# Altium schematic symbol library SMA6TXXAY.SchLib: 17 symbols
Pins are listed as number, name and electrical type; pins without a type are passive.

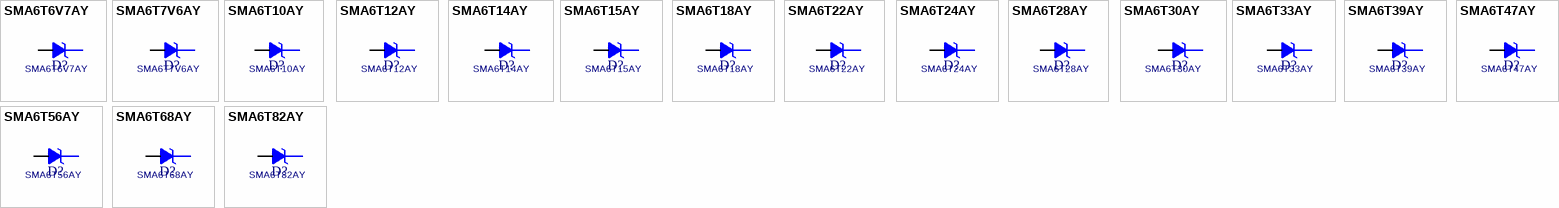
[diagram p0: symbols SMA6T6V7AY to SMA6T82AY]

## SMA6T6V7AY
designator D?
footprint ST_SMA
pins: 1 K, 2 A

## SMA6T7V6AY
designator D?
footprint ST_SMA
pins: 1 K, 2 A

## SMA6T10AY
designator D?
footprint ST_SMA
pins: 1 K, 2 A

## SMA6T12AY
designator D?
footprint ST_SMA
pins: 1 K, 2 A

## SMA6T14AY
designator D?
footprint ST_SMA
pins: 1 K, 2 A

## SMA6T15AY
designator D?
footprint ST_SMA
pins: 1 K, 2 A

## SMA6T18AY
designator D?
footprint ST_SMA
pins: 1 K, 2 A

## SMA6T22AY
designator D?
footprint ST_SMA
pins: 1 K, 2 A

## SMA6T24AY
designator D?
footprint ST_SMA
pins: 1 K, 2 A

## SMA6T28AY
designator D?
footprint ST_SMA
pins: 1 K, 2 A

## SMA6T30AY
designator D?
footprint ST_SMA
pins: 1 K, 2 A

## SMA6T33AY
designator D?
footprint ST_SMA
pins: 1 K, 2 A

## SMA6T39AY
designator D?
footprint ST_SMA
pins: 1 K, 2 A

## SMA6T47AY
designator D?
footprint ST_SMA
pins: 1 K, 2 A

## SMA6T56AY
designator D?
footprint ST_SMA
pins: 1 K, 2 A

## SMA6T68AY
designator D?
footprint ST_SMA
pins: 1 K, 2 A

## SMA6T82AY
designator D?
footprint ST_SMA
pins: 1 K, 2 A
